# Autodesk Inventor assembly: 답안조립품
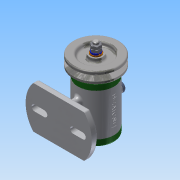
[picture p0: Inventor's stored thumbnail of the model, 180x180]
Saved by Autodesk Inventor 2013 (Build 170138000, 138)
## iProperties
Created: 2017-12
Part Number: 답안조립품
Document SubType Name: Assembly
Designer: Administrator
Author: Administrator
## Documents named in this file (14)
- C:\Users\Administrator\Desktop\471208V1020\답안조립품.iam
- C:\Users\Administrator\Desktop\471208V1020\V벨트풀리.ipt
- C:\Users\Administrator\Desktop\471208V1020\고무캡.ipt
- C:\Users\Administrator\Desktop\471208V1020\너트 M 8.ipt
- C:\Users\Administrator\Desktop\471208V1020\뒤커버.ipt
- C:\Users\Administrator\Desktop\471208V1020\베어링 15 x 32 x 9.ipt
- C:\Users\Administrator\AppData\Local\Temp\Temp1_471208V1020.zip\471208V1020\본체.ipt
- C:\Users\Administrator\Desktop\471208V1020\볼트 M4 x 12.ipt
- C:\Users\Administrator\Desktop\471208V1020\스프링와셔 8.ipt
- C:\Users\Administrator\Desktop\471208V1020\앞커버.ipt
- C:\Users\Administrator\Desktop\471208V1020\오일 실 15 25 7.ipt
- C:\Users\Administrator\Desktop\471208V1020\와셔 8x17.ipt
- C:\Users\Administrator\Desktop\471208V1020\축.ipt
- C:\Users\Administrator\Desktop\471208V1020\키 3 x 3 x 12.ipt
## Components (2 placed, 2 different names)
1. V벨트풀리:1
2. 고무캡:1 — 각도:1
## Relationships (1: Angle 1)
- 각도:1 [Angle]: 고무캡:1
